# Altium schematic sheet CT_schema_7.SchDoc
size 226 x 144 mm
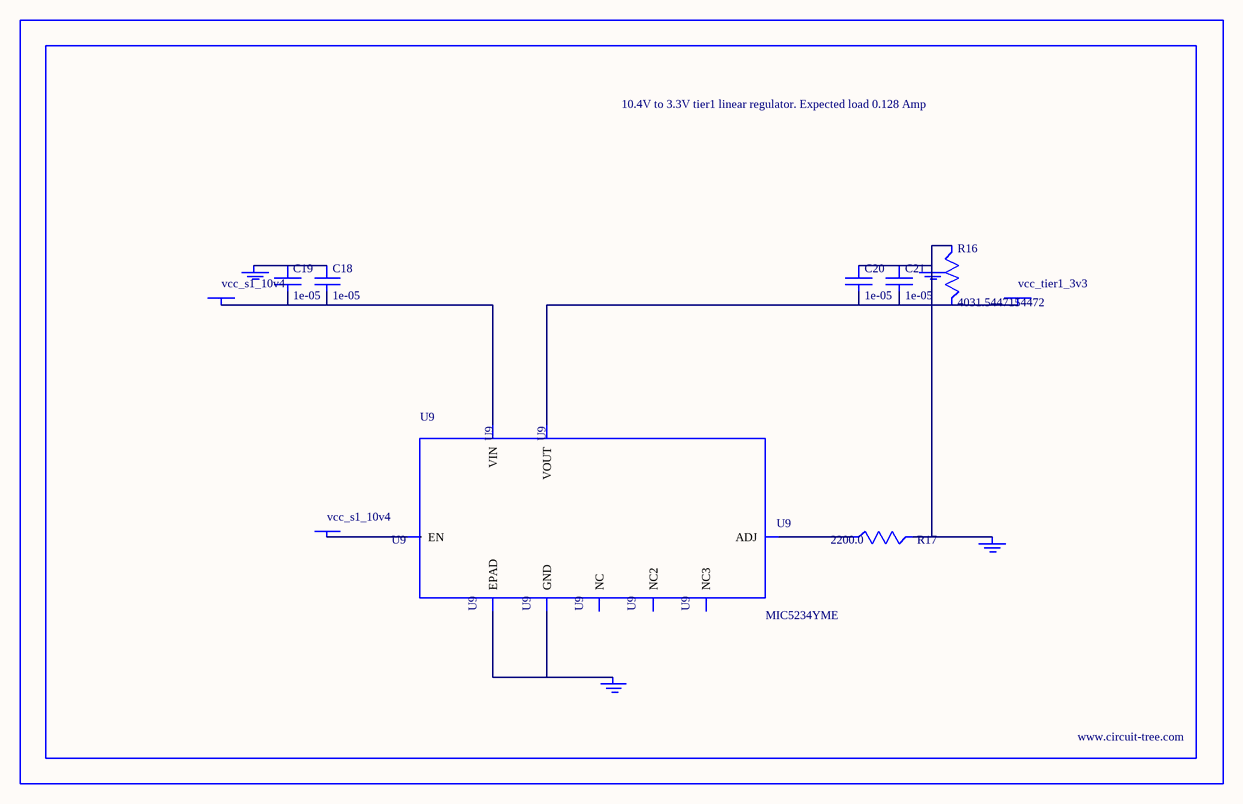
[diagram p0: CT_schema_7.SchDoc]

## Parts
BORDER6  (no value)
C18  1e-05  [C1210]
C19  1e-05  [C1210]
C20  1e-05  [C1210]
C21  1e-05  [C1210]
GND_INSTANCE_6_0  (no value)
GND_INSTANCE_6_1  (no value)
GND_INSTANCE_6_2  (no value)
GND_INSTANCE_6_3  (no value)
POWER_INSTANCE_6_0  vcc_tier1_3v3
POWER_INSTANCE_6_1  vcc_s1_10v4
POWER_INSTANCE_6_2  vcc_s1_10v4
R16  4031.5447154472  [R0603]
R17  2200.0  [R0603]
U9  MIC5234YME  [SOIC-8_EP]

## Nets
NetC18_1: C18.1 C19.1 GND_INSTANCE_6_3.0(GND)
NetC18_2: C18.2 C19.2 POWER_INSTANCE_6_2.0(PWR) U9.8(VIN)
NetC20_1: C20.1 C21.1 GND_INSTANCE_6_0.0(GND) GND_INSTANCE_6_1.0(GND) R16.1 R17.2
NetC20_2: C20.2 C21.2 POWER_INSTANCE_6_0.0(PWR) R16.2 U9.1(VOUT)
NetGND_INSTANCE_6_2_0: GND_INSTANCE_6_2.0(GND) U9.7(GND) U9.EPAD
NetPOWER_INSTANCE_6_1_0: POWER_INSTANCE_6_1.0(PWR) U9.5(EN)
NetR17_1: R17.1 U9.4(ADJ)

Not connected (* = marked no-connect by the designer): U9 2(NC) 3(NC2) 6(NC3)

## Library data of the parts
BORDER6 = BORDER_PAGE6
C18-C21 = C1210C106K5PACTU
GND_INSTANCE_6_0-GND_INSTANCE_6_3 = GND
POWER_INSTANCE_6_0-POWER_INSTANCE_6_2 = PWR
R16 = R16
R17 = RC0603JR-072K2L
